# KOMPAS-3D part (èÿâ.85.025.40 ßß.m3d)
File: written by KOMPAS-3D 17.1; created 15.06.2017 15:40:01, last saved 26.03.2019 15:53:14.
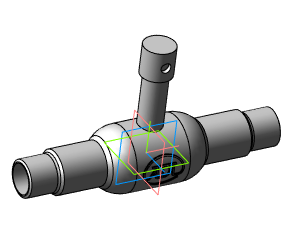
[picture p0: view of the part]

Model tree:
1. Операция без истории:2  (labels: Сталь 20  ГОСТ 1050-88)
